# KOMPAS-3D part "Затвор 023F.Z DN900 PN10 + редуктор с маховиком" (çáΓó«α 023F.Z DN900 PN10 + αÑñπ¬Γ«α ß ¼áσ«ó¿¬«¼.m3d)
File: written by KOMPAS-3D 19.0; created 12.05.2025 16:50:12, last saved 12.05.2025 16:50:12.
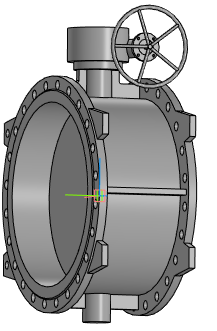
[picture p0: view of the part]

Document properties: Полное имя файла: Затвор 023F.Z DN900 PN10 + редуктор с маховиком.a3d

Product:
- Part/product: Затвор 023F.Z DN900 PN10 + редуктор с маховиком
    Масса: 787.281

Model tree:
1. Операция без истории:1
